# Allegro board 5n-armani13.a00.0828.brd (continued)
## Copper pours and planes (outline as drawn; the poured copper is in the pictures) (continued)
N153375577 on TOP (solid shape): 168.05,83.47 168.05,83.37 168.02,83.24 168.05,83.11 168.05,82.93 168.17,82.81 168.5,82.81 168.66,82.65 168.66,82.22 168.55,82.12 168.25,82.12 168.07,81.94 168.07,81.64 167.69,81.26 166.53,81.26 166.4,81.31 166.26,81.32 166.24,81.31 166.09,81.46 166.09,81.92 166.19,82.02 166.24,82.02 166.42,82.02 166.5,81.94 166.5,81.87 166.52,81.84 167.23,81.84 167.36,81.97 167.36,83.4 167.54,83.58 167.93,83.58
N154204989 on TOP (solid shape): 137.36,105.62 137.36,103.58 137.24,103.46 135.71,103.46 135.41,103.76 135.41,105.97 135.61,106.17 136.8,106.17
N154204989 on BOTTOM (solid shape): 137.47,105.67 137.47,98.58 136.78,97.89 135.43,97.89 135.1,98.22 135.1,99.01 134.85,99.27 133.83,99.27 133.43,99.67 133.43,105.23 133.76,105.56 135.36,105.56 135.46,105.67 135.46,105.97 135.64,106.15 136.98,106.15
N154205542 on BOTTOM (solid shape): 129.72,112.45 129.72,106 129.49,105.77 127.61,105.77 127.25,106.12 127.25,107.19 126.97,107.47 125.93,107.47 125.83,107.57 125.83,112.27 126.15,112.59 127.27,112.59 127.28,112.6 129.57,112.6

Small or netless copper shapes (teardrops, artwork), in the pictures only: 2174 on TOP, 3315 on BOTTOM, 810 on IN1, 280 on IN2, 768 on IN3

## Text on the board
